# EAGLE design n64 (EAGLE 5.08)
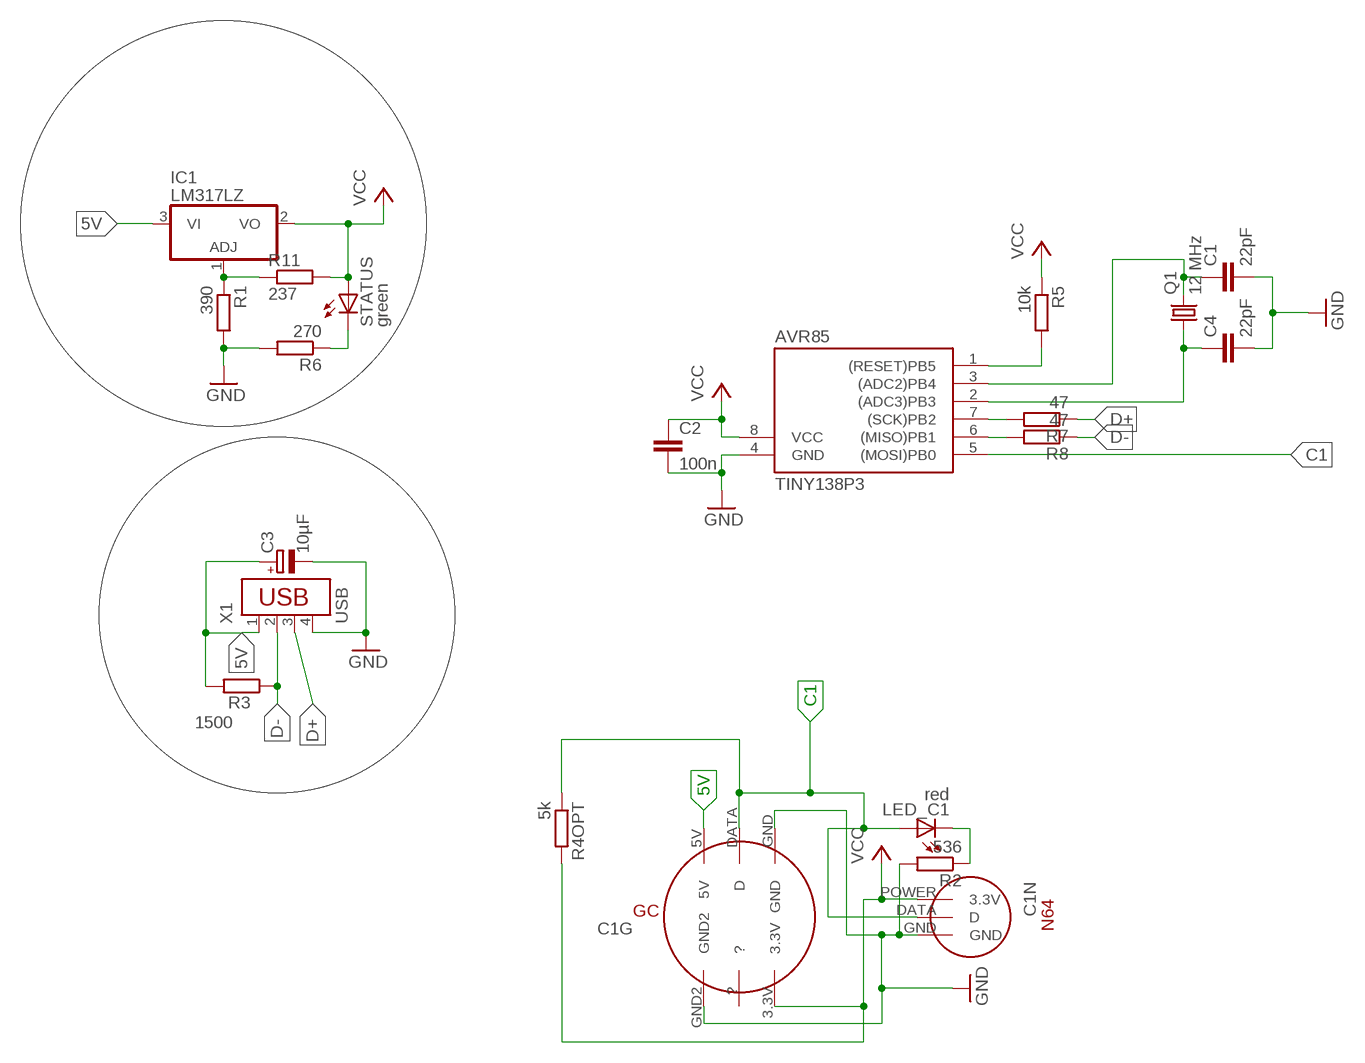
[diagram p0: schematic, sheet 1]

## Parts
AVR85  TINY138P3  [DIL08]
C1  22pF  C2.5/2  [C2.5-2]
C1G  GAMECUBEDEFAULT  [GAMECUBE]
C1N  N64DEFAULT  [N64]
C2  100n  C5/3  [C5B3]
C3  10µF  CPOL-EUE15-5AXIAL  [E15-5]
C4  22pF  C2.5/2  [C2.5-2]
IC1  LM317LZ  [TO92]
LED_C1  red  LEDSQR2X5  [LED2X5]
Q1  12 MHz  CRYSTALHC49S  [HC49/S]
R1  390  R-EU_0207/10  [0207/10]
R2  536  R-EU_0309/V  [0309V]
R3  1500  R-EU_0207/10  [0207/10]
R4OPT  5k  R-EU_0207/10  [0207/10]
R5  10k  R-EU_0207/10  [0207/10]
R6  270  R-EU_0207/10  [0207/10]
R7  47  R-EU_0207/10  [0207/10]
R8  47  R-EU_0207/10  [0207/10]
R11  237  R-EU_0309/V  [0309V]
STATUS  green  LEDSQR2X5  [LED2X5]
X1  USB  USB-787616  [USB]

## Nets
5V: C1G.5V C3.+ IC1.3(VI) R3.2 X1.1
C1: AVR85.5((MOSI)PB0) C1G.DATA(D) C1N.DATA(D) LED_C1.A R4OPT.1
C2: AVR85.2((ADC3)PB3) C4.1 Q1.1
C3: AVR85.3((ADC2)PB4) C1.1 Q1.2
D+: R7.1 X1.3
D-: R3.1 R8.1 X1.2
GND: AVR85.4(GND) C1.2 C1G.GND C1G.GND2 C1N.GND C2.2 C3.- C4.2 R1.2 R2.2 R6.2 X1.4
N$1: R6.1 STATUS.K(C)
N$2: AVR85.1((RESET)PB5) R5.2
N$3: IC1.1(ADJ) R1.1 R11.1
N$4: AVR85.7((SCK)PB2) R7.2
N$5: AVR85.6((MISO)PB1) R8.2
N$6: LED_C1.K(C) R2.1
VCC: AVR85.8(VCC) C1G.3.3V C1N.POWER(3.3V) C2.1 IC1.2(VO) R4OPT.2 R5.1 R11.2 STATUS.A
Unconnected: C1G.?

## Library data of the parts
AVR85 = avr-6:TINY13*
C1 C2 C4 = capacitor-wima:C: CAPACITOR
C1G = n64gc:GAMECUBE
C1N = n64gc:N64
C3 = resistor:CPOL-EU: POLARIZED CAPACITOR, European symbol
IC1 = linear:*317: Positive VOLTAGE REGULATOR
LED_C1 STATUS = led:LED: LED
Q1 = crystal:CRYSTAL: CRYSTAL
R1 R3 R4OPT R5-R8 = rcl:R-EU_: RESISTOR, European symbol
R2 R11 = resistor:R-EU_: RESISTOR, European symbol
X1 = con-amp:USB-787616: AMP connector

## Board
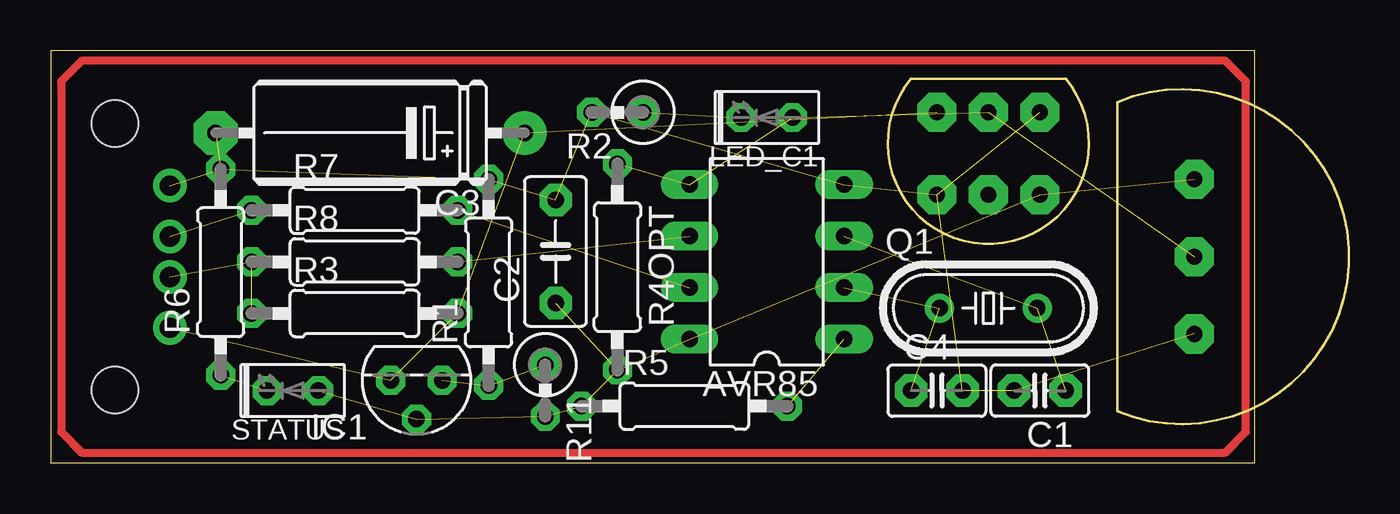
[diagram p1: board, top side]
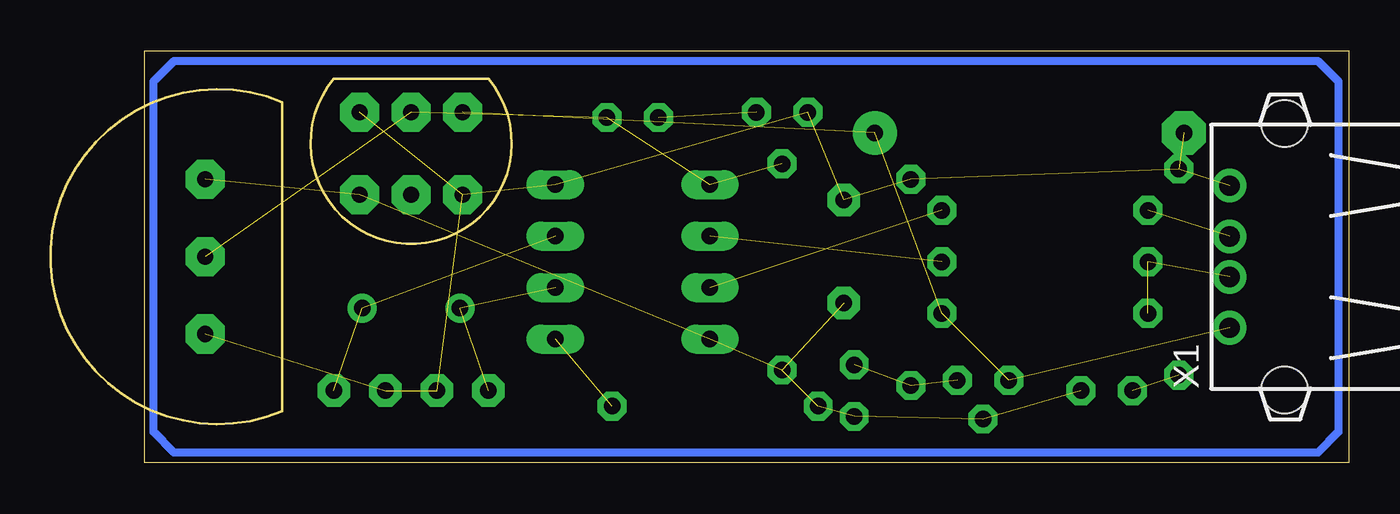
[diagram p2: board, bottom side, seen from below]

Size 64 x 20.31 mm. Coordinates in mm from the lower left corner, seen from the top.
Outline: 0,0 59.36,0 59.36,20.31 0,20.31 0,0
Copper layers (1*16): Top 0.035mm / dielectric 1.5mm / Bottom 0.035mm
Design rules "default *": minimum track width 15mil, minimum drill 32mil, track to track 8mil, track to pad 10mil, pad to pad 10mil, via to via 10mil, smd to smd 0mil, copper to edge 20mil, drill to drill 20mil, minimum pad ring 12mil, minimum via ring 12mil, stop-mask expansion 4mil, vias tented up to drill 0mil, thermal gap 10mil

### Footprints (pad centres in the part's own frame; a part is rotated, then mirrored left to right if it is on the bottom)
DIL08 = drill 0.813 long: 1 -3.81,-3.81; 2 -1.27,-3.81; 3 1.27,-3.81; 4 3.81,-3.81; 5 3.81,3.81; 6 1.27,3.81; 7 -1.27,3.81; 8 -3.81,3.81
C2.5-2 = drill 0.813 pad 1.6 octagon: 1 -1.27,0; 2 1.27,0
GAMECUBE = drill 0.8 pad 1.93 octagon: 3.3V 2.54,-1.27; 5V -2.54,2.794; ? 0,-1.27; DATA 0,2.794; GND 2.54,2.794; GND2 -2.54,-1.27
N64 = drill 0.8 pad 1.93 octagon: DATA 0,-1.27; GND 3.81,-1.27; POWER -3.81,-1.27
C5B3 = drill 0.813 pad 1.6 octagon: 1 -2.54,0; 2 2.54,0
E15-5 = drill 0.813 pad 2.159 round: + -7.62,0 | drill 0.813 pad 2.159 octagon: - 7.62,0
TO92 = drill 0.813 octagon: 1 -1.27,0; 2 0,1.905; 3 1.27,0
LED2X5 = drill 0.813 octagon: A -1.27,0; K 1.27,0
HC49/S = drill 0.813 round: 1 -2.413,0; 2 2.413,0
0207/10 = drill 0.813 octagon: 1 -5.08,0; 2 5.08,0
0309V = drill 0.813 octagon: 1 -1.27,0; 2 1.27,0
USB = drill 1 round: 1 -3.5,12.99; 2 -1,12.99; 3 1,12.99; 4 3.5,12.99 | hole 2.3: -6.57,10.28; 6.57,10.28

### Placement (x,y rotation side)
AVR85  35.31,9.91 90 top
C1  48.77,3.56 180 top
C1G  46.23,14.48 0 top
C1N  57.66,10.16 270 top
C2  24.89,10.41 90 top
C3  15.75,16.26 180 top
C4  43.69,3.56 0 top
IC1  18.03,4.06 180 top
LED_C1  35.31,17.02 180 top
Q1  46.23,7.62 0 top
R1  21.59,8.89 90 top
R2  27.94,17.27 180 top
R3  14.99,7.37 0 top
R4OPT  27.94,9.65 270 top
R5  31.24,2.79 0 top
R6  8.38,9.4 90 top
R7  14.99,12.45 0 top
R8  14.99,9.91 0 top
R11  24.38,3.56 270 top
STATUS  11.94,3.56 180 top
X1  -7.11,10.16 90 bottom

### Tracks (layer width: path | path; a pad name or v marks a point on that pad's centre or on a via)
5V  (4 unrouted)
C1  (4 unrouted)
C2  (2 unrouted)
C3  (2 unrouted)
D+  (1 unrouted)
D-  (2 unrouted)
GND  (11 unrouted)
N$1  (1 unrouted)
N$2  (1 unrouted)
N$3  (2 unrouted)
N$4  (1 unrouted)
N$5  (1 unrouted)
N$6  (1 unrouted)
N$7
  Bottom 0.406: 1.52,0.51 57.91,0.51 58.93,1.52 58.93,18.29 58.93,18.8 57.91,19.81 2.03,19.81 1.52,19.81 0.51,18.8 0.51,1.52 1.52,0.51
N$8
  Top 0.406: 0.51,1.52 1.52,0.51 57.91,0.51 58.93,1.52 58.93,18.8 57.91,19.81 1.52,19.81 0.51,18.8 0.51,1.52
VCC  (8 unrouted)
